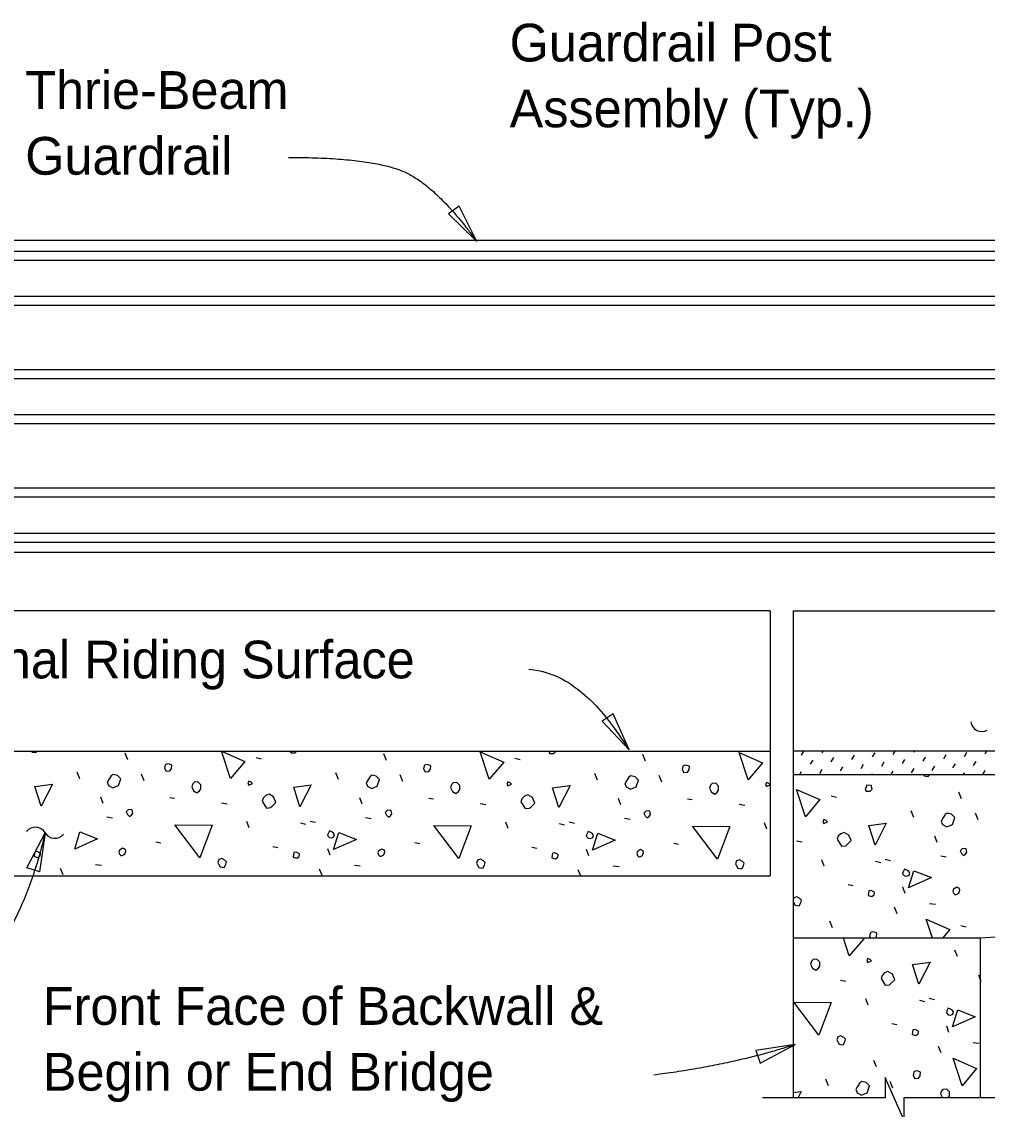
# Model space of a CAD drawing. Extents: x 0 to 41.1, y 0 to 25.9.
# Drawn here: x 2.84 to 8, y 4.8 to 10.61 of the extents above; entities that cross this region are included whole.
import ezdxf

# ---------------------------------------------------------------- set-up
doc = ezdxf.new("R2010")
doc.units = 0
for name, color, linetype in [('Dimension', 7, 'Continuous'), ('ExistSuperStruct', 7, 'Continuous'), ('Miscellaneous', 7, 'Continuous'), ('SteelMisc', 7, 'Continuous'), ('TextStructures', 7, 'Continuous')]:
    doc.layers.add(name, color=color, linetype=linetype)

msp = doc.modelspace()

# ---------------------------------------------------------------- linework, layer by layer
at = {"layer": 'Dimension'}
for points in [[(5.2739, 9.4345), (5.1794, 9.6234), (5.1225, 9.5818)], [(6.0884, 6.7165), (6.0019, 6.9093), (5.9432, 6.87)], [(2.9643, 6.2731), (2.9339, 6.0641), (2.8667, 6.0858)], [(6.9754, 5.1413), (6.7666, 5.1094), (6.7888, 5.0424)]]:
    msp.add_lwpolyline(points, close=True, dxfattribs=at)
msp.add_lwpolyline([(8.2539, 4.8554), (7.5569, 4.8554), (7.5569, 4.7391), (7.4575, 4.9641), (7.4575, 4.8554), (6.8023, 4.8554)], dxfattribs=at)
for centre, start, end in [((7.9742, 6.8743), 187.95358, 299.6808), ((2.912, 6.2435), 30.00813, 141.73535), ((3.0152, 6.3031), 210.00813, 321.73535)]:
    msp.add_arc(centre, 0.0596, start, end, dxfattribs=at)
for points, degree in [([(4.2654, 9.8844), (4.6871, 9.8844), (5.0469, 9.745), (5.2739, 9.4345)], 2), ([(5.5515, 7.1486), (5.6933, 7.1342), (5.8702, 7.0041), (5.9676, 6.8969), (6.0883, 6.7165)], 3), ([(2.9644, 6.2731), (2.7489, 5.3695), (2.13, 5.2717)], 2), ([(6.9755, 5.1413), (6.6476, 5.0328), (6.2205, 4.978)], 2)]:
    msp.add_open_spline(points, degree=degree, dxfattribs=at)
at = {"layer": 'ExistSuperStruct'}
for p, q in [((6.8429, 7.4599), (0.6692, 7.4599)), ((6.8429, 7.4598), (6.8429, 6.0432)), ((6.9655, 7.4599), (6.9655, 4.8552)), ((6.9655, 7.4599), (14.9126, 7.4599)), ((0.6692, 6.71), (6.8429, 6.71)), ((17.3289, 6.71), (6.9655, 6.71)), ((6.9655, 6.585), (17.3289, 6.585)), ((0.6692, 6.0432), (6.8429, 6.0432)), ((12.1854, 5.9599), (7.9654, 5.7099)), ((7.9654, 5.7099), (6.9654, 5.7099)), ((7.9654, 5.7099), (7.9654, 4.8552))]:
    msp.add_line(p, q, dxfattribs=at)
at = {"layer": 'Miscellaneous'}
for p, q in [((3.4057, 6.6633), (3.3916, 6.6986)), ((4.7904, 6.6598), (4.7762, 6.6951)), ((6.1751, 6.6562), (6.1609, 6.6916)), ((7.0099, 6.6887), (7.0222, 6.71)), ((7.1205, 6.7016), (7.1254, 6.71)), ((7.28, 6.6658), (7.2929, 6.6882)), ((7.3906, 6.6787), (7.4036, 6.7011)), ((7.5012, 6.6917), (7.5118, 6.71)), ((7.6119, 6.7047), (7.615, 6.71)), ((7.7713, 6.6688), (7.7843, 6.6912)), ((7.882, 6.6818), (7.8949, 6.7041)), ((7.9926, 6.6947), (8.0015, 6.71)), ((4.0921, 6.6757), (4.1204, 6.6686)), ((5.4768, 6.6721), (5.5051, 6.6651)), ((7.0587, 6.6398), (7.0717, 6.6622)), ((7.1693, 6.6528), (7.1823, 6.6752)), ((7.3288, 6.6169), (7.3418, 6.6393)), ((7.4394, 6.6299), (7.4524, 6.6523)), ((7.5501, 6.6429), (7.563, 6.6653)), ((7.6607, 6.6558), (7.6737, 6.6782)), ((7.7095, 6.607), (7.7225, 6.6294)), ((7.8202, 6.62), (7.8331, 6.6423)), ((7.9308, 6.6329), (7.9438, 6.6553)), ((3.1494, 6.5625), (3.1352, 6.5979)), ((3.4935, 6.5508), (3.4793, 6.5861)), ((4.534, 6.559), (4.5199, 6.5943)), ((4.8781, 6.5472), (4.864, 6.5826)), ((5.9187, 6.5555), (5.9046, 6.5908)), ((6.2628, 6.5437), (6.2487, 6.5791)), ((7.0009, 6.585), (7.0099, 6.6004)), ((7.1075, 6.591), (7.1205, 6.6134)), ((7.2182, 6.604), (7.2311, 6.6264)), ((7.3874, 6.585), (7.3906, 6.5905)), ((7.4905, 6.585), (7.5012, 6.6035)), ((7.5989, 6.594), (7.6119, 6.6164)), ((7.877, 6.585), (7.882, 6.5935)), ((7.9801, 6.585), (7.9926, 6.6065)), ((3.2749, 6.4299), (3.2625, 6.4635)), ((3.6313, 6.4624), (3.6561, 6.4589)), ((4.6596, 6.4264), (4.6472, 6.46)), ((5.016, 6.4589), (5.0408, 6.4553)), ((6.0442, 6.4229), (6.0319, 6.4565)), ((6.4007, 6.4553), (6.4254, 6.4518)), ((7.1684, 6.4712), (7.1966, 6.4641)), ((7.8666, 6.4553), (7.8525, 6.4906)), ((3.9071, 6.4341), (3.9372, 6.4288)), ((5.2918, 6.4306), (5.3218, 6.4253)), ((6.6765, 6.427), (6.7065, 6.4217)), ((3.2937, 6.3581), (3.3238, 6.3528)), ((4.6784, 6.3546), (4.7084, 6.3493)), ((6.0631, 6.351), (6.0931, 6.3457)), ((7.6103, 6.3545), (7.5962, 6.3898)), ((7.9544, 6.3427), (7.9402, 6.3781)), ((4.0556, 6.2998), (4.0432, 6.3333)), ((4.3296, 6.3263), (4.3579, 6.3192)), ((4.382, 6.3362), (4.4103, 6.3292)), ((5.4403, 6.2962), (5.4279, 6.3298)), ((5.7143, 6.3227), (5.7426, 6.3157)), ((5.7667, 6.3327), (5.795, 6.3256)), ((6.825, 6.2927), (6.8126, 6.3263)), ((3.5571, 6.2255), (3.5836, 6.2202)), ((4.9418, 6.222), (4.9683, 6.2167)), ((6.9834, 6.2296), (7.0134, 6.2243)), ((7.7358, 6.2219), (7.7234, 6.2555)), ((4.1829, 6.2008), (4.2094, 6.1955)), ((4.4881, 6.1537), (4.4757, 6.1872)), ((5.5676, 6.1972), (5.5941, 6.1919)), ((5.8728, 6.1501), (5.8604, 6.1837)), ((6.3265, 6.2184), (6.353, 6.2131)), ((7.1319, 6.0953), (7.1195, 6.1288)), ((7.4059, 6.1218), (7.4342, 6.1147)), ((7.4583, 6.1318), (7.4866, 6.1247)), ((7.7546, 6.1501), (7.7847, 6.1448)), ((3.061, 6.0476), (3.0468, 6.0829)), ((3.2336, 6.1035), (3.2654, 6.1)), ((4.4457, 6.0441), (4.4315, 6.0794)), ((4.6183, 6.1), (4.6501, 6.0965)), ((5.8293, 6.0432), (5.8162, 6.0759)), ((6.003, 6.0965), (6.0348, 6.0929)), ((7.2591, 5.9963), (7.2857, 5.991)), ((7.5643, 5.9492), (7.552, 5.9827)), ((7.5219, 5.8396), (7.5078, 5.8749)), ((7.6945, 5.8955), (7.7263, 5.892)), ((7.1761, 5.7647), (7.1619, 5.8)), ((7.8625, 5.7771), (7.8908, 5.77)), ((7.845, 5.611), (7.8309, 5.6464)), ((6.9655, 5.5111), (6.967, 5.5109)), ((7.2181, 5.4861), (7.2481, 5.4808)), ((7.9705, 5.4784), (7.9581, 5.512)), ((7.3666, 5.3518), (7.3542, 5.3854)), ((7.6406, 5.3783), (7.6688, 5.3712)), ((7.693, 5.3883), (7.7213, 5.3812)), ((7.4938, 5.2528), (7.5204, 5.2475)), ((7.799, 5.2057), (7.7867, 5.2393)), ((7.7566, 5.0961), (7.7425, 5.1314)), ((7.9292, 5.152), (7.961, 5.1485)), ((7.4108, 5.0212), (7.3966, 5.0566)), ((7.1544, 4.9205), (7.1403, 4.9558)), ((7.4985, 4.9087), (7.4844, 4.9441))]:
    msp.add_line(p, q, dxfattribs=at)
for points in [[(2.8923, 6.7099), (2.8948, 6.7039), (2.8913, 6.7075)], [(2.8948, 6.7039), (2.916, 6.7039), (2.922, 6.7099)], [(3.9548, 6.5632), (3.9071, 6.7099), (4.0326, 6.6551), (3.9548, 6.5632)], [(4.2754, 6.7099), (4.2795, 6.7004), (4.276, 6.7039)], [(4.2795, 6.7004), (4.3007, 6.7004), (4.3102, 6.7099)], [(5.3395, 6.5596), (5.2918, 6.7063), (5.4173, 6.6515), (5.3395, 6.5596)], [(5.6592, 6.7099), (5.6589, 6.7092), (5.6642, 6.6969), (5.6606, 6.7004)], [(5.6642, 6.6969), (5.6854, 6.6969), (5.696, 6.7075), (5.6953, 6.7099)], [(6.7242, 6.5561), (6.6765, 6.7028), (6.802, 6.648), (6.7242, 6.5561)], [(3.6031, 6.618), (3.6119, 6.602), (3.6313, 6.6038), (3.6402, 6.6162), (3.642, 6.6356), (3.6296, 6.6409), (3.6207, 6.6427), (3.6101, 6.6392), (3.6066, 6.6356), (3.6031, 6.618)], [(4.9877, 6.6144), (4.9966, 6.5985), (5.016, 6.6003), (5.0249, 6.6126), (5.0266, 6.6321), (5.0143, 6.6374), (5.0054, 6.6392), (4.9948, 6.6356), (4.9913, 6.6321), (4.9877, 6.6144)], [(6.3724, 6.6109), (6.3813, 6.595), (6.4007, 6.5967), (6.4095, 6.6091), (6.4113, 6.6286), (6.3989, 6.6339), (6.3901, 6.6356), (6.3795, 6.6321), (6.376, 6.6286), (6.3724, 6.6109)], [(3.3032, 6.5254), (3.3261, 6.513), (3.3562, 6.5254), (3.3686, 6.5625), (3.3509, 6.5802), (3.3279, 6.5855), (3.3173, 6.5784), (3.3049, 6.559), (3.2961, 6.5431), (3.3032, 6.5254)], [(4.6878, 6.5219), (4.7108, 6.5095), (4.7409, 6.5219), (4.7533, 6.559), (4.7356, 6.5767), (4.7126, 6.582), (4.702, 6.5749), (4.6896, 6.5555), (4.6808, 6.5395), (4.6878, 6.5219)], [(6.0725, 6.5183), (6.0955, 6.506), (6.1256, 6.5183), (6.1379, 6.5555), (6.1202, 6.5731), (6.0973, 6.5784), (6.0867, 6.5714), (6.0743, 6.5519), (6.0654, 6.536), (6.0725, 6.5183)], [(7.6626, 6.585), (7.6669, 6.5772), (7.6881, 6.5737), (7.6943, 6.585)], [(2.9425, 6.4158), (2.909, 6.5201), (3.0026, 6.5325), (2.9425, 6.4158)], [(3.748, 6.519), (3.7586, 6.4977), (3.7763, 6.4871), (3.7904, 6.4977), (3.7975, 6.5083), (3.7975, 6.5296), (3.7816, 6.5455), (3.7622, 6.5437), (3.7533, 6.5349), (3.748, 6.519)], [(4.0538, 6.5278), (4.0733, 6.5366), (4.0662, 6.5437), (4.0538, 6.549), (4.0485, 6.5366), (4.0538, 6.5278)], [(4.3272, 6.4123), (4.2936, 6.5166), (4.3873, 6.5289), (4.3272, 6.4123)], [(5.1327, 6.5154), (5.1433, 6.4942), (5.161, 6.4836), (5.1751, 6.4942), (5.1822, 6.5048), (5.1822, 6.526), (5.1663, 6.5419), (5.1468, 6.5402), (5.138, 6.5313), (5.1327, 6.5154)], [(5.4385, 6.5243), (5.458, 6.5331), (5.4509, 6.5402), (5.4385, 6.5455), (5.4332, 6.5331), (5.4385, 6.5243)], [(5.7119, 6.4087), (5.6783, 6.513), (5.772, 6.5254), (5.7119, 6.4087)], [(6.5174, 6.5119), (6.528, 6.4907), (6.5457, 6.4801), (6.5598, 6.4907), (6.5669, 6.5013), (6.5669, 6.5225), (6.551, 6.5384), (6.5315, 6.5366), (6.5227, 6.5278), (6.5174, 6.5119)], [(6.8232, 6.5207), (6.8426, 6.5296), (6.8356, 6.5366), (6.8232, 6.5419), (6.8179, 6.5296), (6.8232, 6.5207)], [(7.3557, 6.4959), (7.377, 6.4959), (7.3876, 6.5065), (7.3823, 6.526), (7.3593, 6.5277), (7.3557, 6.5171), (7.3504, 6.5083), (7.3557, 6.4959), (7.3522, 6.4994)], [(4.1246, 6.4429), (4.1475, 6.4058), (4.1705, 6.4076), (4.1794, 6.4164), (4.1988, 6.4359), (4.1864, 6.4659), (4.1617, 6.4801), (4.144, 6.473), (4.1299, 6.4589), (4.1246, 6.4429)], [(5.5092, 6.4394), (5.5322, 6.4023), (5.5552, 6.4041), (5.564, 6.4129), (5.5835, 6.4323), (5.5711, 6.4624), (5.5464, 6.4765), (5.5287, 6.4695), (5.5145, 6.4553), (5.5092, 6.4394)], [(7.0311, 6.3587), (6.9834, 6.5054), (7.1089, 6.4506), (7.0311, 6.3587)], [(3.4051, 6.3705), (3.4157, 6.3599), (3.4263, 6.3669), (3.4334, 6.3775), (3.4298, 6.3952), (3.421, 6.397), (3.4086, 6.3952), (3.398, 6.3846), (3.4051, 6.3705)], [(4.7897, 6.3669), (4.8004, 6.3563), (4.811, 6.3634), (4.818, 6.374), (4.8145, 6.3917), (4.8057, 6.3934), (4.7933, 6.3917), (4.7827, 6.3811), (4.7897, 6.3669)], [(6.1744, 6.3634), (6.185, 6.3528), (6.1956, 6.3599), (6.2027, 6.3705), (6.1992, 6.3881), (6.1903, 6.3899), (6.178, 6.3881), (6.1674, 6.3775), (6.1744, 6.3634)], [(7.1301, 6.3233), (7.1495, 6.3321), (7.1425, 6.3392), (7.1301, 6.3445), (7.1248, 6.3321), (7.1301, 6.3233)], [(7.7641, 6.3174), (7.7871, 6.305), (7.8171, 6.3174), (7.8295, 6.3545), (7.8118, 6.3722), (7.7888, 6.3775), (7.7782, 6.3704), (7.7659, 6.351), (7.757, 6.335), (7.7641, 6.3174)], [(3.7922, 6.1389), (3.6579, 6.3157), (3.8576, 6.3139), (3.7922, 6.1389)], [(4.4845, 6.2479), (4.4969, 6.2461), (4.5093, 6.2514), (4.5128, 6.262), (4.5075, 6.2708), (4.4969, 6.2779), (4.4845, 6.2832), (4.4775, 6.2691), (4.4739, 6.2585), (4.4845, 6.2479)], [(5.1769, 6.1354), (5.0425, 6.3121), (5.2423, 6.3104), (5.1769, 6.1354)], [(5.8692, 6.2443), (5.8816, 6.2426), (5.894, 6.2479), (5.8975, 6.2585), (5.8922, 6.2673), (5.8816, 6.2744), (5.8692, 6.2797), (5.8622, 6.2655), (5.8586, 6.2549), (5.8692, 6.2443)], [(6.5616, 6.1318), (6.4272, 6.3086), (6.627, 6.3068), (6.5616, 6.1318)], [(7.4035, 6.2078), (7.3699, 6.3121), (7.4636, 6.3244), (7.4035, 6.2078)], [(3.1222, 6.1866), (3.1505, 6.2785), (3.2442, 6.2414), (3.1222, 6.1866)], [(4.5069, 6.1831), (4.5352, 6.275), (4.6289, 6.2379), (4.5069, 6.1831)], [(5.8916, 6.1795), (5.9199, 6.2715), (6.0136, 6.2343), (5.8916, 6.1795)], [(7.2008, 6.2384), (7.2238, 6.2013), (7.2468, 6.2031), (7.2556, 6.2119), (7.2751, 6.2314), (7.2627, 6.2614), (7.2379, 6.2756), (7.2203, 6.2685), (7.2061, 6.2544), (7.2008, 6.2384)], [(2.906, 6.146), (2.9255, 6.1407), (2.9379, 6.1495), (2.9396, 6.1619), (2.9361, 6.1654), (2.922, 6.1725), (2.9096, 6.1707), (2.9078, 6.1583), (2.906, 6.146)], [(3.3697, 6.1513), (3.3768, 6.1513), (3.3909, 6.1583), (3.3962, 6.1742), (3.3945, 6.1831), (3.3803, 6.1902), (3.3626, 6.1795), (3.3591, 6.1689), (3.3626, 6.1583), (3.3697, 6.1513)], [(4.2907, 6.1424), (4.3102, 6.1371), (4.3225, 6.146), (4.3243, 6.1583), (4.3208, 6.1619), (4.3066, 6.1689), (4.2943, 6.1672), (4.2925, 6.1548), (4.2907, 6.1424)], [(4.7544, 6.1477), (4.7615, 6.1477), (4.7756, 6.1548), (4.7809, 6.1707), (4.7791, 6.1795), (4.765, 6.1866), (4.7473, 6.176), (4.7438, 6.1654), (4.7473, 6.1548), (4.7544, 6.1477)], [(5.6754, 6.1389), (5.6948, 6.1336), (5.7072, 6.1424), (5.709, 6.1548), (5.7055, 6.1583), (5.6913, 6.1654), (5.6789, 6.1636), (5.6772, 6.1513), (5.6754, 6.1389)], [(6.1391, 6.1442), (6.1461, 6.1442), (6.1603, 6.1513), (6.1656, 6.1672), (6.1638, 6.176), (6.1497, 6.1831), (6.132, 6.1725), (6.1285, 6.1619), (6.132, 6.1513), (6.1391, 6.1442)], [(7.866, 6.1624), (7.8766, 6.1518), (7.8872, 6.1589), (7.8943, 6.1695), (7.8908, 6.1872), (7.8819, 6.1889), (7.8695, 6.1872), (7.8589, 6.1766), (7.866, 6.1624)], [(3.8912, 6.1071), (3.9, 6.0912), (3.9213, 6.0876), (3.9301, 6.1035), (3.9336, 6.1177), (3.9248, 6.1265), (3.9089, 6.1354), (3.893, 6.13), (3.8877, 6.1141), (3.8912, 6.1071)], [(5.2759, 6.1035), (5.2847, 6.0876), (5.3059, 6.0841), (5.3148, 6.1), (5.3183, 6.1141), (5.3095, 6.123), (5.2936, 6.1318), (5.2777, 6.1265), (5.2723, 6.1106), (5.2759, 6.1035)], [(6.6606, 6.1), (6.6694, 6.0841), (6.6906, 6.0805), (6.6995, 6.0965), (6.703, 6.1106), (6.6941, 6.1194), (6.6782, 6.1283), (6.6623, 6.123), (6.657, 6.1071), (6.6606, 6.1)], [(7.5608, 6.0434), (7.5732, 6.0416), (7.5856, 6.0469), (7.5891, 6.0575), (7.5838, 6.0663), (7.5732, 6.0734), (7.5608, 6.0787), (7.5537, 6.0646), (7.5502, 6.054), (7.5608, 6.0434)], [(7.5832, 5.9786), (7.6114, 6.0705), (7.7051, 6.0334), (7.5832, 5.9786)], [(6.9675, 5.9026), (6.9763, 5.8867), (6.9975, 5.8831), (7.0064, 5.899), (7.0099, 5.9132), (7.001, 5.922), (6.9851, 5.9309), (6.9692, 5.9255), (6.9655, 5.9142)], [(7.367, 5.9379), (7.3864, 5.9326), (7.3988, 5.9415), (7.4006, 5.9538), (7.397, 5.9574), (7.3829, 5.9644), (7.3705, 5.9627), (7.3687, 5.9503), (7.367, 5.9379)], [(7.8306, 5.9432), (7.8377, 5.9432), (7.8519, 5.9503), (7.8572, 5.9662), (7.8554, 5.975), (7.8413, 5.9821), (7.8236, 5.9715), (7.82, 5.9609), (7.8236, 5.9503), (7.8306, 5.9432)], [(6.9655, 5.9066), (6.9675, 5.9026)], [(7.7105, 5.7099), (7.6775, 5.8113), (7.803, 5.7565), (7.7636, 5.7099)], [(7.2658, 5.6152), (7.235, 5.7099)], [(7.3371, 5.7099), (7.3436, 5.7071), (7.2658, 5.6152)], [(7.4051, 5.7099), (7.4105, 5.7176), (7.4123, 5.737), (7.3999, 5.7423), (7.3911, 5.7441), (7.3805, 5.7406), (7.377, 5.737), (7.3734, 5.7193)], [(7.3734, 5.7193), (7.3787, 5.7099)], [(7.059, 5.571), (7.0696, 5.5498), (7.0872, 5.5392), (7.1014, 5.5498), (7.1085, 5.5604), (7.1085, 5.5816), (7.0926, 5.5975), (7.0731, 5.5957), (7.0643, 5.5869), (7.059, 5.571)], [(7.3648, 5.5798), (7.3842, 5.5887), (7.3772, 5.5957), (7.3648, 5.601), (7.3595, 5.5887), (7.3648, 5.5798)], [(7.4355, 5.495), (7.4585, 5.4579), (7.4815, 5.4596), (7.4903, 5.4685), (7.5097, 5.4879), (7.4974, 5.518), (7.4726, 5.5321), (7.4549, 5.525), (7.4408, 5.5109), (7.4355, 5.495)], [(7.6382, 5.4643), (7.6046, 5.5686), (7.6983, 5.581), (7.6382, 5.4643)], [(7.1032, 5.1909), (6.9688, 5.3677), (7.1686, 5.3659), (7.1032, 5.1909)], [(7.7955, 5.2999), (7.8079, 5.2981), (7.8202, 5.3034), (7.8238, 5.314), (7.8185, 5.3229), (7.8079, 5.33), (7.7955, 5.3353), (7.7884, 5.3211), (7.7849, 5.3105), (7.7955, 5.2999)], [(7.8179, 5.2351), (7.8461, 5.327), (7.9398, 5.2899), (7.8179, 5.2351)], [(7.2022, 5.1591), (7.211, 5.1432), (7.2322, 5.1397), (7.241, 5.1556), (7.2446, 5.1697), (7.2357, 5.1785), (7.2198, 5.1874), (7.2039, 5.1821), (7.1986, 5.1662), (7.2022, 5.1591)], [(7.6017, 5.1945), (7.6211, 5.1892), (7.6335, 5.198), (7.6353, 5.2104), (7.6317, 5.2139), (7.6176, 5.221), (7.6052, 5.2192), (7.6034, 5.2068), (7.6017, 5.1945)], [(7.8688, 4.9211), (7.8211, 5.0678), (7.9466, 5.013), (7.8688, 4.9211)], [(7.6081, 4.9759), (7.617, 4.96), (7.6364, 4.9617), (7.6452, 4.9741), (7.647, 4.9936), (7.6346, 4.9989), (7.6258, 5.0006), (7.6152, 4.9971), (7.6117, 4.9936), (7.6081, 4.9759)], [(7.3082, 4.8833), (7.3312, 4.871), (7.3613, 4.8833), (7.3736, 4.9205), (7.356, 4.9381), (7.333, 4.9434), (7.3224, 4.9364), (7.31, 4.9169), (7.3011, 4.901), (7.3082, 4.8833)], [(6.9655, 4.8848), (7.0077, 4.8904), (6.9896, 4.8553)], [(7.795, 4.8553), (7.7955, 4.8557), (7.8026, 4.8663), (7.8026, 4.8875), (7.7867, 4.9034), (7.7672, 4.9016), (7.7584, 4.8928), (7.7531, 4.8769)], [(7.7531, 4.8769), (7.7637, 4.8557), (7.7643, 4.8553)]]:
    msp.add_lwpolyline(points, dxfattribs=at)
at = {"layer": 'SteelMisc'}
for p, q in [((12.7651, 9.4391), (0.6692, 9.4391)), ((0.6692, 9.3835), (12.7651, 9.3835)), ((0.6692, 9.3353), (12.7651, 9.3353)), ((0.6692, 9.1425), (12.7651, 9.1425)), ((0.6692, 9.0943), (12.7651, 9.0943)), ((0.6692, 8.7503), (12.7651, 8.7503)), ((0.6692, 8.7021), (12.7651, 8.7021)), ((0.6692, 8.5093), (12.7651, 8.5093)), ((0.6692, 8.4611), (12.7651, 8.4611)), ((0.6692, 8.1172), (12.7651, 8.1172)), ((0.6692, 8.069), (12.7651, 8.069)), ((0.6692, 7.8761), (12.7651, 7.8761)), ((0.6692, 7.8279), (12.7651, 7.8279)), ((12.7651, 7.7724), (0.6692, 7.7724))]:
    msp.add_line(p, q, dxfattribs=at)

# ---------------------------------------------------------------- texts
at = {"layer": 'Dimension'}
for s, p in [('Guardrail Post ', (5.4489, 10.3972)), ('Thrie-Beam ', (2.8577, 10.1439)), ('Assembly (Typ.)', (5.4489, 10.0452)), ('Guardrail', (2.8577, 9.7919)), ('Front Face of Backwall &', (2.9518, 5.2465)), ('Begin or End Bridge', (2.9518, 4.8945))]:
    msp.add_text(s, height=0.2016, dxfattribs=at).set_placement(p)
at = {"layer": 'TextStructures'}
msp.add_text('Final Riding Surface', height=0.2016, dxfattribs=at).set_placement((2.5134, 7.0989))

doc.saveas('drawing.dxf')
